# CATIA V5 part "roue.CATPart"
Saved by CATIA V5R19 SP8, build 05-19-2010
Part number: Part1
Publications: "diamètre_roue"
Bounding box of the stored display mesh (mm): x -99.819 to 99.819, y -70 to 10, z -100 to 100
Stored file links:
  G:\EU_thinkMotion\CFAO_2010\SIL_groupe2\SIL_groupe2\A reprendre\fnongaibaa\fnongaibaa\roue.CATPart
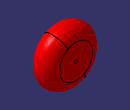
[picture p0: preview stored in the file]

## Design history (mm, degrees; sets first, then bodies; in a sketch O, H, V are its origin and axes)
Parameters
  `largeur roue` = 10 mm
  `diamètre_roue` = 80 mm
Body1 (main body)
  Sketch1 on yz-plane, origin (0, 0, 0), H (0, 1, 0), V (0, 0, 1)
    line L1 (10, 60) -> (10, 0)
    line L2 (10, 0) -> (-70, 0)
    line L3 (-70, 0) -> (-70, 60)
    point P1 (10, 0)
    arc A1 centre (-30, 60) radius 40 from (-70, 60) to (10, 60) cw
    length L1 = 60
    length L2 = 80 {= `diamètre_roue`}
    horizontal: L2 H
    vertical: L1 V, L3 V
    coincidence: P1 H
    tangency: A1 L3, A1 L1
  Shaft1: profile Sketch1, axis Sketch1.L2, angle 360
  Sketch2 on face of Shaft1 from Sketch1.L1, origin (0, 10, 0), H (1, 0, 0), V (0, 0, -1)
    point P1 (0, 0)
  Hole1: placed by Sketch2, at (0, 10, 0) direction (0, -1, 0), diameter 10, up to face of Shaft1 from Sketch1.L3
